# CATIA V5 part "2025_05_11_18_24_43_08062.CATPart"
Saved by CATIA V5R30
Part number: 2025_05_11_18_24_43_08062
Definition: 2025_05_11_18_24_43_0806
Nomenclature: 2025_05_11_18_24_43_0806
Source: Unknown
Description: PART--DESC
Bounding box of the stored display mesh (mm): x -12.75 to 12.75, y -12.75 to 12.75, z 0 to 53
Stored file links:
  E:\Bakalarka\Model\Forma_v7\2025_05_11_18_24_43_08062.CATPart
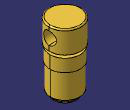
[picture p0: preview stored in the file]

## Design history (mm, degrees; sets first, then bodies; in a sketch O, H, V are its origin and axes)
Body1 "MANIFOLD_SOLID_BREP #164" (main body)
  Solid1: solid without history
  DatumSurface1
  DatumSurface2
